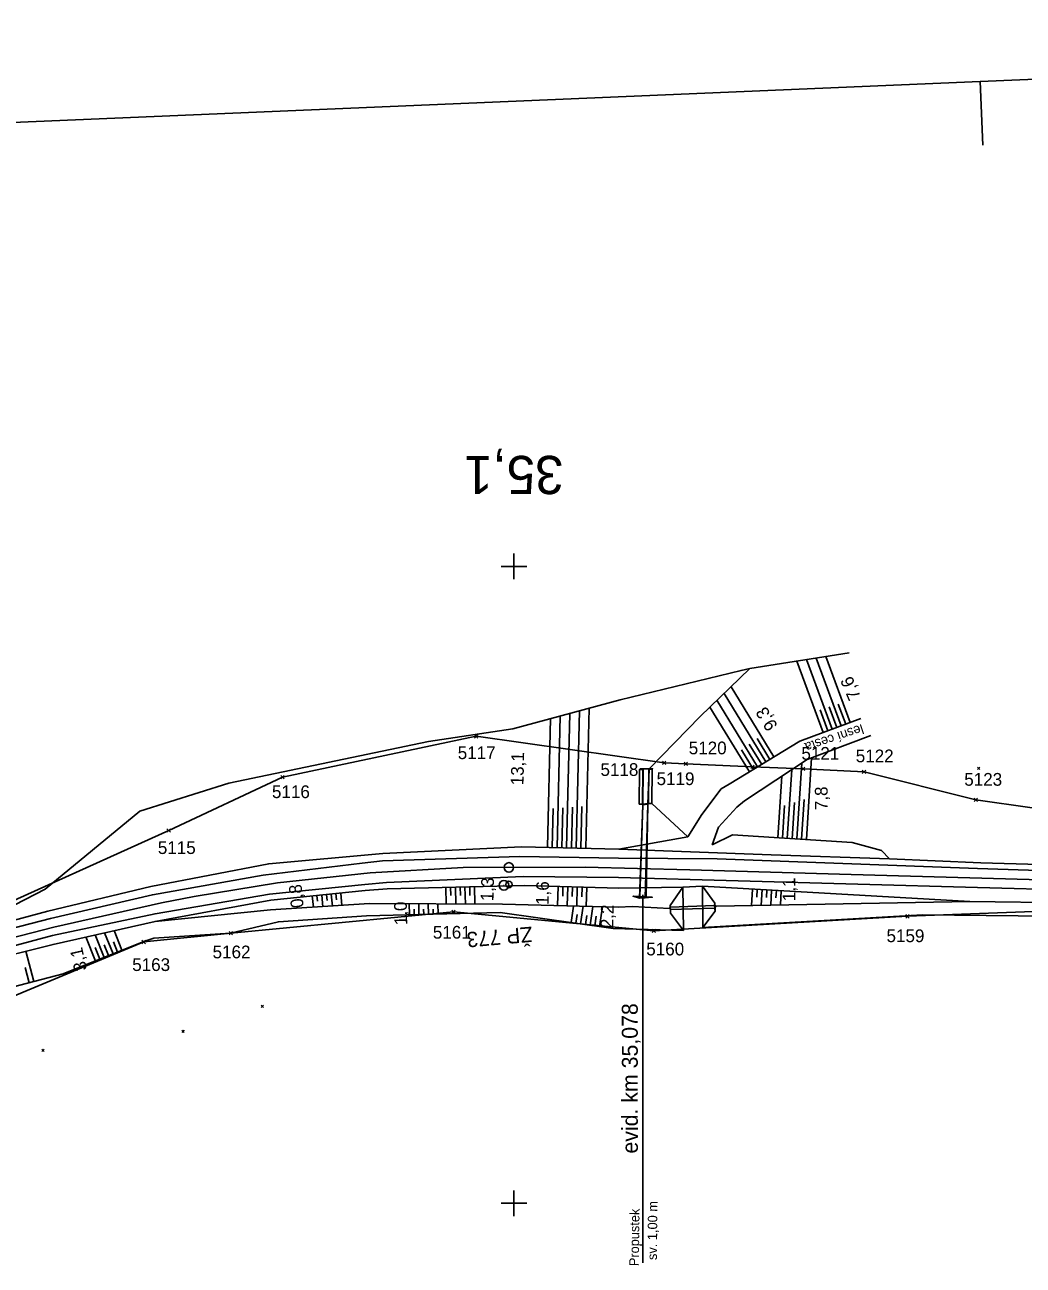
# Model space of a CAD drawing. Extents: x -806456 to -805395, y -1150847 to -1150506.
# Drawn here: x -805976.8 to -805820, y -1150709.7 to -1150515 of the extents above; entities that cross this region are included whole.
import ezdxf

# ---------------------------------------------------------------- set-up
doc = ezdxf.new("R2010")
doc.units = 0
for name, color, linetype in [('0381KM032-037P - Vrstva 1', 7, 'Continuous'), ('0381KM032-037P - Vrstva 19', 7, 'Continuous'), ('0381KM032-037P - Vrstva 4', 7, 'Continuous'), ('0381KM032-037P - Vrstva 48', 7, 'Continuous'), ('0381KM032-037P - Vrstva 49', 7, 'Continuous'), ('0381KM032-037P - Vrstva 51', 7, 'Continuous'), ('0381KM032-037P - Vrstva 7', 7, 'Continuous'), ('formát', 7, 'Continuous'), ('krizky_1000 - Vrstva 1', 7, 'Continuous'), ('szdc - hran DP', 7, 'Continuous'), ('szdc - szdc_cislo', 7, 'Continuous'), ('szdc - szdc_krizek', 7, 'Continuous'), ('vyt_sit - stávající', 7, 'Continuous')]:
    doc.layers.add(name, color=color, linetype=linetype)

msp = doc.modelspace()

# ---------------------------------------------------------------- linework, layer by layer
at = {"layer": '0381KM032-037P - Vrstva 1'}
for points in [[(-805907.99, -1150647.29), (-805922.59, -1150648.1), (-805937.12, -1150649.71), (-805950.23, -1150651.85), (-805955.36, -1150652.84)], [(-805872.37, -1150647.65), (-805888.81, -1150647.23), (-805907.99, -1150647.29)], [(-805647.61, -1150654.06), (-805666.7, -1150653.55), (-805695.88, -1150652.69), (-805700.7, -1150652.54), (-805736.3, -1150651.55), (-805773.14, -1150650.48), (-805809.82, -1150649.4), (-805847.04, -1150648.36), (-805872.37, -1150647.65)], [(-805955.36, -1150652.84), (-805972.27, -1150656.66), (-805989.76, -1150661.17)]]:
    msp.add_lwpolyline(points, dxfattribs=at)
at = {"layer": '0381KM032-037P - Vrstva 19'}
for p, q in [((-805880.33, -1150637.33), (-805880.27, -1150631.9)), ((-805880.27, -1150631.9), (-805880.21, -1150631.81)), ((-805879.77, -1150631.9), (-805880.27, -1150631.9)), ((-805879.71, -1150631.81), (-805880.21, -1150631.81)), ((-805878.75, -1150631.78), (-805879.71, -1150631.81)), ((-805878.81, -1150631.82), (-805878.31, -1150631.82)), ((-805878.75, -1150631.78), (-805878.25, -1150631.78)), ((-805878.37, -1150637.24), (-805878.31, -1150631.82)), ((-805878.31, -1150631.82), (-805878.25, -1150631.78)), ((-805879.83, -1150637.33), (-805880.33, -1150637.33)), ((-805879.78, -1150637.42), (-805880.28, -1150652.07)), ((-805879.78, -1150637.42), (-805880.23, -1150651.86)), ((-805878.87, -1150637.24), (-805879.83, -1150637.33)), ((-805878.96, -1150637.32), (-805879.78, -1150637.42)), ((-805879.78, -1150637.42), (-805878.96, -1150637.32)), ((-805878.96, -1150637.32), (-805879.38, -1150652.05)), ((-805878.96, -1150637.32), (-805879.27, -1150651.81)), ((-805878.87, -1150637.24), (-805878.37, -1150637.24)), ((-805879.79, -1150709.36), (-805879.79, -1150651.59)), ((-805868.51, -1150653.23), (-805875.47, -1150653.52)), ((-805875.46, -1150653.52), (-805868.51, -1150653.23)), ((-805875.43, -1150653.86), (-805868.49, -1150653.67)), ((-805875.43, -1150653.87), (-805868.5, -1150653.67))]:
    msp.add_line(p, q, dxfattribs=at)
for points in [[(-805879.78, -1150637.42), (-805879.83, -1150637.33), (-805879.77, -1150631.9), (-805879.71, -1150631.81)], [(-805878.81, -1150631.82), (-805878.75, -1150631.78), (-805878.96, -1150637.32), (-805878.87, -1150637.24)], [(-805879.38, -1150652.05), (-805880.28, -1150652.07), (-805881.3, -1150651.8), (-805878.28, -1150651.94)]]:
    msp.add_lwpolyline(points, close=True, dxfattribs=at)
for points in [[(-805880.28, -1150652.07), (-805880.23, -1150651.86), (-805879.27, -1150651.81), (-805879.38, -1150652.05)], [(-805875.47, -1150653.27), (-805875.43, -1150654.45), (-805875.43, -1150653.87), (-805875.43, -1150653.86), (-805875.47, -1150653.52), (-805875.46, -1150653.52), (-805875.47, -1150653.27)], [(-805868.49, -1150652.87), (-805868.42, -1150654.14), (-805868.5, -1150653.67), (-805868.49, -1150653.67), (-805868.51, -1150653.23), (-805868.51, -1150653.23), (-805868.49, -1150652.87)]]:
    msp.add_lwpolyline(points, dxfattribs=at)
at = {"layer": '0381KM032-037P - Vrstva 4'}
for points in [[(-805920.59, -1150645.08), (-805938.49, -1150646.69), (-805957, -1150650.24), (-805973.18, -1150654.13), (-805996.94, -1150660.52), (-806010.57, -1150664.04), (-806045.29, -1150673.07), (-806070.44, -1150679.45), (-806076.44, -1150680.94), (-806080.95, -1150682.04), (-806094.16, -1150685.34), (-806107.83, -1150689.09)], [(-805687.98, -1150651.47), (-805728.71, -1150650.4), (-805771.75, -1150649.09), (-805796.82, -1150648.44), (-805827.25, -1150647.42), (-805868.08, -1150645.94), (-805883.57, -1150645.79), (-805899.1, -1150645.56), (-805920.66, -1150646.24), (-805923.83, -1150646.61)], [(-805734.36, -1150649.18), (-805786.14, -1150647.68), (-805826.72, -1150646.54), (-805841.05, -1150645.92), (-805859.62, -1150645.3), (-805883.54, -1150644.38), (-805898.84, -1150644.02), (-805920.59, -1150645.08)], [(-805923.83, -1150646.61), (-805939.39, -1150648.49), (-805956.78, -1150651.56), (-805972.77, -1150655.27), (-805996.74, -1150661.47), (-806010.38, -1150665.11), (-806045.15, -1150673.98), (-806070.28, -1150680.43), (-806094.02, -1150686.67), (-806107.78, -1150690.05)], [(-805688.15, -1150654.42), (-805728.36, -1150653.2), (-805771.94, -1150652.19), (-805796.53, -1150651.28), (-805827.23, -1150650.42), (-805883.58, -1150648.86), (-805898.54, -1150648.68), (-805920.02, -1150649.65), (-805923.42, -1150649.97)], [(-805923.37, -1150650.9), (-805938.15, -1150652.42), (-805956.35, -1150655.74), (-805972.37, -1150659.35), (-805995.12, -1150665.03), (-806009.04, -1150668.86), (-806027.1, -1150673.31), (-806034.62, -1150675.7), (-806043.91, -1150677.85), (-806068.97, -1150684.48)], [(-805923.42, -1150649.97), (-805938.4, -1150651.47), (-805956.35, -1150654.55), (-805972.44, -1150657.98), (-805995.68, -1150664.21)], [(-805687.42, -1150655.93), (-805728.29, -1150654.47), (-805772.22, -1150653.64), (-805796.51, -1150653.02), (-805828.44, -1150652.6), (-805870.39, -1150650.22), (-805873.51, -1150650.39), (-805883.54, -1150650.55), (-805898.37, -1150650.08), (-805919.92, -1150650.63), (-805923.37, -1150650.9)]]:
    msp.add_lwpolyline(points, dxfattribs=at)
at = {"layer": '0381KM032-037P - Vrstva 48'}
for p, q in [((-805848.61, -1150625.04), (-805852.55, -1150614.39)), ((-805847.21, -1150624.52), (-805851.04, -1150614.15)), ((-805851.43, -1150626.08), (-805855.57, -1150614.87)), ((-805850.02, -1150625.56), (-805854.06, -1150614.63)), ((-805860.47, -1150630.7), (-805867.02, -1150619.96)), ((-805859.19, -1150629.92), (-805865.92, -1150618.89)), ((-805888.73, -1150644.26), (-805888.21, -1150622.28)), ((-805863.03, -1150632.26), (-805869.23, -1150622.1)), ((-805861.75, -1150631.48), (-805868.13, -1150621.03)), ((-805849.32, -1150625.3), (-805850.51, -1150622.06)), ((-805847.91, -1150624.78), (-805849.08, -1150621.63)), ((-805894.73, -1150644.11), (-805894.25, -1150623.91)), ((-805893.23, -1150644.15), (-805892.74, -1150623.5)), ((-805891.73, -1150644.19), (-805891.23, -1150623.09)), ((-805890.23, -1150644.22), (-805889.72, -1150622.69)), ((-805850.72, -1150625.82), (-805851.95, -1150622.5)), ((-805861.11, -1150631.09), (-805863.05, -1150627.91)), ((-805859.83, -1150630.31), (-805861.82, -1150627.04)), ((-805862.39, -1150631.87), (-805864.28, -1150628.78)), ((-805854.09, -1150642.9), (-805853.28, -1150630.06)), ((-805857.09, -1150642.71), (-805856.4, -1150631.92)), ((-805855.59, -1150642.8), (-805854.83, -1150630.89)), ((-805858.59, -1150642.61), (-805857.97, -1150632.95)), ((-805890.98, -1150644.2), (-805890.83, -1150637.81)), ((-805889.48, -1150644.24), (-805889.33, -1150637.71)), ((-805857.84, -1150642.66), (-805857.51, -1150637.55)), ((-805856.34, -1150642.76), (-805855.98, -1150637.08)), ((-805854.84, -1150642.85), (-805854.45, -1150636.61)), ((-805893.98, -1150644.13), (-805893.83, -1150638)), ((-805892.48, -1150644.17), (-805892.33, -1150637.91)), ((-805929.45, -1150651.52), (-805929.35, -1150652.46)), ((-805928.7, -1150651.45), (-805928.51, -1150653.34)), ((-805927.96, -1150651.37), (-805927.86, -1150652.33)), ((-805927.21, -1150651.29), (-805927.01, -1150653.25)), ((-805910.7, -1150650.4), (-805910.63, -1150653.02)), ((-805909.95, -1150650.38), (-805909.92, -1150651.7)), ((-805909.2, -1150650.36), (-805909.13, -1150653.02)), ((-805908.45, -1150650.34), (-805908.42, -1150651.68)), ((-805907.7, -1150650.32), (-805907.63, -1150653.02)), ((-805906.95, -1150650.3), (-805906.92, -1150651.66)), ((-805906.2, -1150650.28), (-805906.13, -1150653.02)), ((-805893.06, -1150650.25), (-805893.15, -1150653.26)), ((-805892.31, -1150650.27), (-805892.35, -1150651.78)), ((-805891.56, -1150650.3), (-805891.65, -1150653.3)), ((-805890.81, -1150650.32), (-805890.85, -1150651.82)), ((-805890.06, -1150650.34), (-805890.15, -1150653.34)), ((-805889.31, -1150650.37), (-805889.35, -1150651.86)), ((-805888.56, -1150650.39), (-805888.65, -1150653.38)), ((-805862.55, -1150650.67), (-805862.69, -1150653.23)), ((-805861.8, -1150650.71), (-805861.87, -1150651.96)), ((-805861.05, -1150650.75), (-805861.19, -1150653.2)), ((-805860.3, -1150650.79), (-805860.37, -1150651.99)), ((-805859.55, -1150650.84), (-805859.69, -1150653.17)), ((-805858.8, -1150650.88), (-805858.87, -1150652.02)), ((-805858.06, -1150650.92), (-805858.18, -1150653.15)), ((-805931.69, -1150651.75), (-805931.5, -1150653.53)), ((-805930.94, -1150651.68), (-805930.85, -1150652.58)), ((-805930.19, -1150651.6), (-805930.01, -1150653.44)), ((-805916.42, -1150654.68), (-805916.46, -1150653.01)), ((-805914.92, -1150654.65), (-805914.96, -1150653.01)), ((-805913.42, -1150654.61), (-805913.46, -1150653.01)), ((-805911.92, -1150654.57), (-805911.96, -1150653.01)), ((-805891.01, -1150655.91), (-805890.65, -1150653.33)), ((-805889.53, -1150656.12), (-805889.14, -1150653.37)), ((-805888.04, -1150656.33), (-805887.63, -1150653.41)), ((-805886.56, -1150656.54), (-805886.12, -1150653.45)), ((-805915.67, -1150654.66), (-805915.69, -1150653.84)), ((-805914.17, -1150654.63), (-805914.19, -1150653.82)), ((-805912.67, -1150654.59), (-805912.69, -1150653.8)), ((-805890.27, -1150656.01), (-805890.08, -1150654.68)), ((-805888.79, -1150656.22), (-805888.58, -1150654.8)), ((-805887.3, -1150656.44), (-805887.09, -1150654.93)), ((-805961.55, -1150660.28), (-805962.79, -1150657.19)), ((-805965.72, -1150661.96), (-805967.24, -1150658.19)), ((-805964.33, -1150661.4), (-805965.76, -1150657.86)), ((-805962.94, -1150660.84), (-805964.27, -1150657.52)), ((-805962.24, -1150660.56), (-805962.89, -1150658.96)), ((-805975.4, -1150665.2), (-805976.65, -1150660.41)), ((-805965.03, -1150661.68), (-805965.76, -1150659.85)), ((-805963.64, -1150661.12), (-805964.33, -1150659.41)), ((-805976.13, -1150665.38), (-805976.75, -1150662.99))]:
    msp.add_line(p, q, dxfattribs=at)
at = {"layer": '0381KM032-037P - Vrstva 49'}
for p, q in [((-805827.2, -1150631.55), (-805826.85, -1150631.9)), ((-805827.2, -1150631.9), (-805826.85, -1150631.55)), ((-805883.54, -1150644.38), (-805898.84, -1150644.02)), ((-805873.4, -1150657.16), (-805873.51, -1150650.39)), ((-805868.18, -1150653.33), (-805828.44, -1150652.6)), ((-805939.34, -1150668.9), (-805939.69, -1150669.26)), ((-805939.69, -1150668.9), (-805939.34, -1150669.25)), ((-805952.13, -1150672.84), (-805951.77, -1150673.19)), ((-805951.77, -1150672.84), (-805952.12, -1150673.19)), ((-805973.79, -1150675.81), (-805974.14, -1150676.16)), ((-805974.14, -1150675.81), (-805973.79, -1150676.16))]:
    msp.add_line(p, q, dxfattribs=at)
for points in [[(-805847.37, -1150613.56), (-805862.98, -1150616.05), (-805864.35, -1150616.33), (-805883.33, -1150620.98), (-805900.2, -1150625.5), (-805913.4, -1150627.48)], [(-805862.98, -1150616.05), (-805870.78, -1150623.59), (-805878.75, -1150631.78)], [(-805845.56, -1150623.91), (-805855.14, -1150627.45), (-805866.22, -1150634.21), (-805867.47, -1150634.93), (-805870.51, -1150638.97), (-805872.7, -1150642.46)], [(-805973.62, -1150650.67), (-805958.72, -1150638.45), (-805944.76, -1150634.02), (-805913.4, -1150627.48)], [(-805868.9, -1150643.71), (-805867.89, -1150640.94), (-805864.99, -1150637.81), (-805863.82, -1150636.79), (-805853.97, -1150630.32), (-805843.97, -1150626.57)], [(-805878.75, -1150631.78), (-805878.25, -1150631.78), (-805878.31, -1150631.82), (-805878.37, -1150637.24), (-805872.7, -1150642.46)], [(-805872.7, -1150642.46), (-805883.54, -1150644.38)], [(-805868.9, -1150643.71), (-805865.69, -1150642.16), (-805846.9, -1150643.36)], [(-805846.9, -1150643.36), (-805842.28, -1150644.6), (-805841.05, -1150645.92)], [(-805920.59, -1150645.08), (-805938.49, -1150646.69)], [(-805883.54, -1150644.38), (-805898.84, -1150644.02), (-805920.59, -1150645.08)], [(-806076.44, -1150680.94), (-806070.44, -1150679.45), (-806045.29, -1150673.07), (-806010.57, -1150664.04), (-805996.94, -1150660.52), (-805973.18, -1150654.13), (-805957, -1150650.24), (-805938.49, -1150646.69)], [(-805786.14, -1150647.68), (-805826.72, -1150646.54), (-805841.05, -1150645.92)], [(-805973.62, -1150650.67), (-805978.37, -1150653.15), (-805984.72, -1150655.91), (-805997.34, -1150657.28), (-806027.21, -1150661.72), (-806046.76, -1150671.15)], [(-805923.37, -1150650.9), (-805938.15, -1150652.42), (-805956.35, -1150655.74), (-805972.37, -1150659.35), (-805995.12, -1150665.03)], [(-805873.51, -1150650.39), (-805883.54, -1150650.55), (-805898.37, -1150650.08), (-805919.92, -1150650.63), (-805923.37, -1150650.9)], [(-805873.51, -1150650.39), (-805875.47, -1150653.27), (-805875.46, -1150653.52), (-805875.59, -1150653.71)], [(-805687.42, -1150655.93), (-805728.29, -1150654.47), (-805772.22, -1150653.64), (-805796.51, -1150653.02), (-805828.44, -1150652.6), (-805870.39, -1150650.22)], [(-805687.58, -1150660.02), (-805738.95, -1150663.31), (-805774.06, -1150657.65), (-805795.8, -1150655.14), (-805835.84, -1150654.7), (-805870.36, -1150656.71), (-805870.39, -1150650.22)], [(-805870.36, -1150656.71), (-805868.42, -1150654.14), (-805868.5, -1150653.67), (-805868.18, -1150653.33), (-805868.51, -1150653.23), (-805868.49, -1150652.87), (-805870.39, -1150650.22)], [(-805922.71, -1150652.93), (-805938.23, -1150653.94), (-805956.35, -1150655.74)], [(-805875.59, -1150653.71), (-805881.41, -1150653.41), (-805883.63, -1150653.51), (-805901.81, -1150653.03), (-805922.71, -1150652.93)], [(-805923.15, -1150654.86), (-805936.98, -1150655.81), (-805944.5, -1150657.57), (-805956.52, -1150658.37), (-805958.13, -1150658.91), (-805970.8, -1150664), (-805994.63, -1150670.19)], [(-805873.4, -1150657.16), (-805884.43, -1150656.84), (-805902.18, -1150654.32), (-805923.15, -1150654.86)], [(-805875.59, -1150653.71), (-805875.43, -1150653.87), (-805875.43, -1150654.45), (-805873.4, -1150657.16)]]:
    msp.add_lwpolyline(points, dxfattribs=at)
at = {"layer": '0381KM032-037P - Vrstva 51'}
for points in [[(-805872.7, -1150642.46), (-805870.51, -1150638.97), (-805867.47, -1150634.93), (-805866.22, -1150634.21), (-805855.14, -1150627.45), (-805845.56, -1150623.91)], [(-805867.47, -1150634.93), (-805866.22, -1150634.21), (-805855.14, -1150627.45), (-805845.56, -1150623.91)], [(-805864.99, -1150637.81), (-805863.82, -1150636.79), (-805853.97, -1150630.32), (-805843.97, -1150626.57)], [(-805872.7, -1150642.46), (-805870.51, -1150638.97), (-805867.47, -1150634.93)], [(-805868.9, -1150643.71), (-805867.89, -1150640.94), (-805864.99, -1150637.81)]]:
    msp.add_lwpolyline(points, dxfattribs=at)
at = {"layer": '0381KM032-037P - Vrstva 7'}
msp.add_line((-805900.84, -1150649.94), (-805900.74, -1150649.94), dxfattribs=at)
for centre, radius in [((-805900.8, -1150647.27), 0.75), ((-805900.79, -1150649.94), 0.5)]:
    msp.add_circle(centre, radius, dxfattribs=at)
at = {"layer": 'formát'}
for p, q in [((-805617.02, -1150514.97), (-805826.83, -1150523.88)), ((-805826.83, -1150523.88), (-806456.26, -1150550.6)), ((-805826.83, -1150523.88), (-805826.4, -1150533.87))]:
    msp.add_line(p, q, dxfattribs=at)
at = {"layer": 'krizky_1000 - Vrstva 1'}
for points in [[(-805900, -1150598), (-805900, -1150602)], [(-805902, -1150600), (-805898, -1150600)], [(-805900, -1150698), (-805900, -1150702)], [(-805902, -1150700), (-805898, -1150700)]]:
    msp.add_lwpolyline(points, dxfattribs=at)
at = {"layer": 'szdc - hran DP'}
for p, q in [((-805936.34, -1150633.1), (-805905.92, -1150626.68)), ((-805905.92, -1150626.68), (-805876.4, -1150630.84)), ((-805876.4, -1150630.84), (-805873.01, -1150630.99)), ((-805873.01, -1150630.99), (-805862.56, -1150631.46)), ((-805862.56, -1150631.46), (-805854.6, -1150631.81)), ((-805854.6, -1150631.81), (-805845.04, -1150632.24)), ((-805954.21, -1150641.47), (-805936.34, -1150633.1)), ((-805845.04, -1150632.24), (-805827.46, -1150636.65)), ((-805827.46, -1150636.65), (-805818.65, -1150637.92)), ((-805984.31, -1150655.05), (-805954.21, -1150641.47)), ((-805909.49, -1150654.26), (-805944.43, -1150657.58)), ((-805878.04, -1150657.24), (-805909.49, -1150654.26)), ((-805838.22, -1150654.94), (-805878.04, -1150657.24)), ((-805807.41, -1150653.77), (-805838.22, -1150654.94)), ((-805958.14, -1150658.97), (-805982.42, -1150669.1)), ((-805944.43, -1150657.58), (-805958.14, -1150658.97))]:
    msp.add_line(p, q, dxfattribs=at)
at = {"layer": 'szdc - szdc_krizek'}
for p, q in [((-805905.66, -1150626.95), (-805906.19, -1150626.42)), ((-805906.19, -1150626.95), (-805905.66, -1150626.42)), ((-805876.14, -1150631.1), (-805876.67, -1150630.57)), ((-805876.67, -1150631.1), (-805876.14, -1150630.57)), ((-805872.74, -1150631.26), (-805873.28, -1150630.73)), ((-805873.28, -1150631.26), (-805872.74, -1150630.73)), ((-805862.3, -1150631.73), (-805862.83, -1150631.2)), ((-805862.83, -1150631.73), (-805862.3, -1150631.2)), ((-805854.33, -1150632.07), (-805854.87, -1150631.54)), ((-805854.87, -1150632.07), (-805854.33, -1150631.54)), ((-805844.78, -1150632.51), (-805845.31, -1150631.98)), ((-805845.31, -1150632.51), (-805844.78, -1150631.98)), ((-805936.08, -1150633.36), (-805936.61, -1150632.83)), ((-805936.61, -1150633.36), (-805936.08, -1150632.83)), ((-805827.2, -1150636.92), (-805827.73, -1150636.39)), ((-805827.73, -1150636.92), (-805827.2, -1150636.39)), ((-805953.95, -1150641.74), (-805954.48, -1150641.21)), ((-805954.48, -1150641.74), (-805953.95, -1150641.21)), ((-805909.22, -1150654.53), (-805909.76, -1150654)), ((-805909.76, -1150654.53), (-805909.22, -1150654)), ((-805837.96, -1150655.21), (-805838.49, -1150654.68)), ((-805838.49, -1150655.21), (-805837.96, -1150654.68)), ((-805944.17, -1150657.84), (-805944.7, -1150657.31)), ((-805944.7, -1150657.84), (-805944.17, -1150657.31)), ((-805877.78, -1150657.51), (-805878.31, -1150656.98)), ((-805878.31, -1150657.51), (-805877.78, -1150656.98)), ((-805957.88, -1150659.24), (-805958.41, -1150658.71)), ((-805958.41, -1150659.24), (-805957.88, -1150658.71))]:
    msp.add_line(p, q, dxfattribs=at)
at = {"layer": 'vyt_sit - stávající'}
msp.add_line((-805901.64, -1150650.08), (-805901.54, -1150650.08), dxfattribs=at)
msp.add_circle((-805901.58, -1150650.08), 0.756, dxfattribs=at)

# ---------------------------------------------------------------- texts
at = {"layer": '0381KM032-037P - Vrstva 19'}
for s, height, rotation, p in [('evid. km 35,078', 2.5, 90.0485, (-805880.55, -1150692.19)), ('sv. 1,00 m', 1.5, 89.3778, (-805877.56, -1150708.91)), (' Propustek', 1.5, 89.2433, (-805880.41, -1150710.44))]:
    msp.add_text(s, height=height, rotation=rotation, dxfattribs=at).set_placement(p)
at = {"layer": '0381KM032-037P - Vrstva 48'}
for s, rotation, p in [('7,6', 113.3216, (-805845.52, -1150620.49)), ('9,3', 121.2221, (-805858.53, -1150625.04)), ('13,1', 88.6293, (-805898.52, -1150634.39)), ('7,8', 90.583, (-805850.73, -1150638.27)), ('1,3', 88.4218, (-805903.23, -1150652.58)), ('1,6', 88.4623, (-805894.58, -1150653.18)), ('1,1', 90.4951, (-805855.82, -1150652.56)), ('0,8', 95.8667, (-805933, -1150653.53)), ('1,0', 91.4666, (-805916.75, -1150656.32)), ('2,2', 88.3753, (-805884.43, -1150656.84)), ('3,1', 102.684, (-805967.01, -1150663.31))]:
    msp.add_text(s, height=2, rotation=rotation, dxfattribs=at).set_placement(p)
at = {"layer": '0381KM032-037P - Vrstva 51'}
msp.add_text('lesní cesta', height=1.5, rotation=198.6145, dxfattribs=at).set_placement((-805845.41, -1150624.74))
at = {"layer": '0381KM032-037P - Vrstva 7'}
msp.add_text('35,1', height=6, rotation=180, dxfattribs=at).set_placement((-805892.22, -1150582.65))
at = {"layer": 'szdc - szdc_cislo'}
for s, p in [('5120', (-805872.56, -1150629.51)), ('5117', (-805908.83, -1150630.26)), ('5121', (-805854.87, -1150630.36)), ('5122', (-805846.34, -1150630.76)), ('5118', (-805886.42, -1150632.9)), ('5119', (-805877.61, -1150634.34)), ('5123', (-805829.3, -1150634.44)), ('5116', (-805938, -1150636.38)), ('5115', (-805955.92, -1150645.16)), ('5161', (-805912.74, -1150658.45)), ('5159', (-805841.51, -1150659)), ('5160', (-805879.23, -1150661.08)), ('5162', (-805947.32, -1150661.54)), ('5163', (-805959.94, -1150663.53))]:
    msp.add_text(s, height=2, dxfattribs=at).set_placement(p)
at = {"layer": 'vyt_sit - stávající'}
msp.add_text('ŽP 773', height=2.4, rotation=185, dxfattribs=at).set_placement((-805897.19, -1150656.55))

doc.saveas('drawing.dxf')
